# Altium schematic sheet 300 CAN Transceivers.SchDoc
size Letter; Organization: Toradex Solutions Inc.; Address1: 6415 Northwest Drive; Address2: Mississauga, ON, L4V 1X1; Address3: Canada
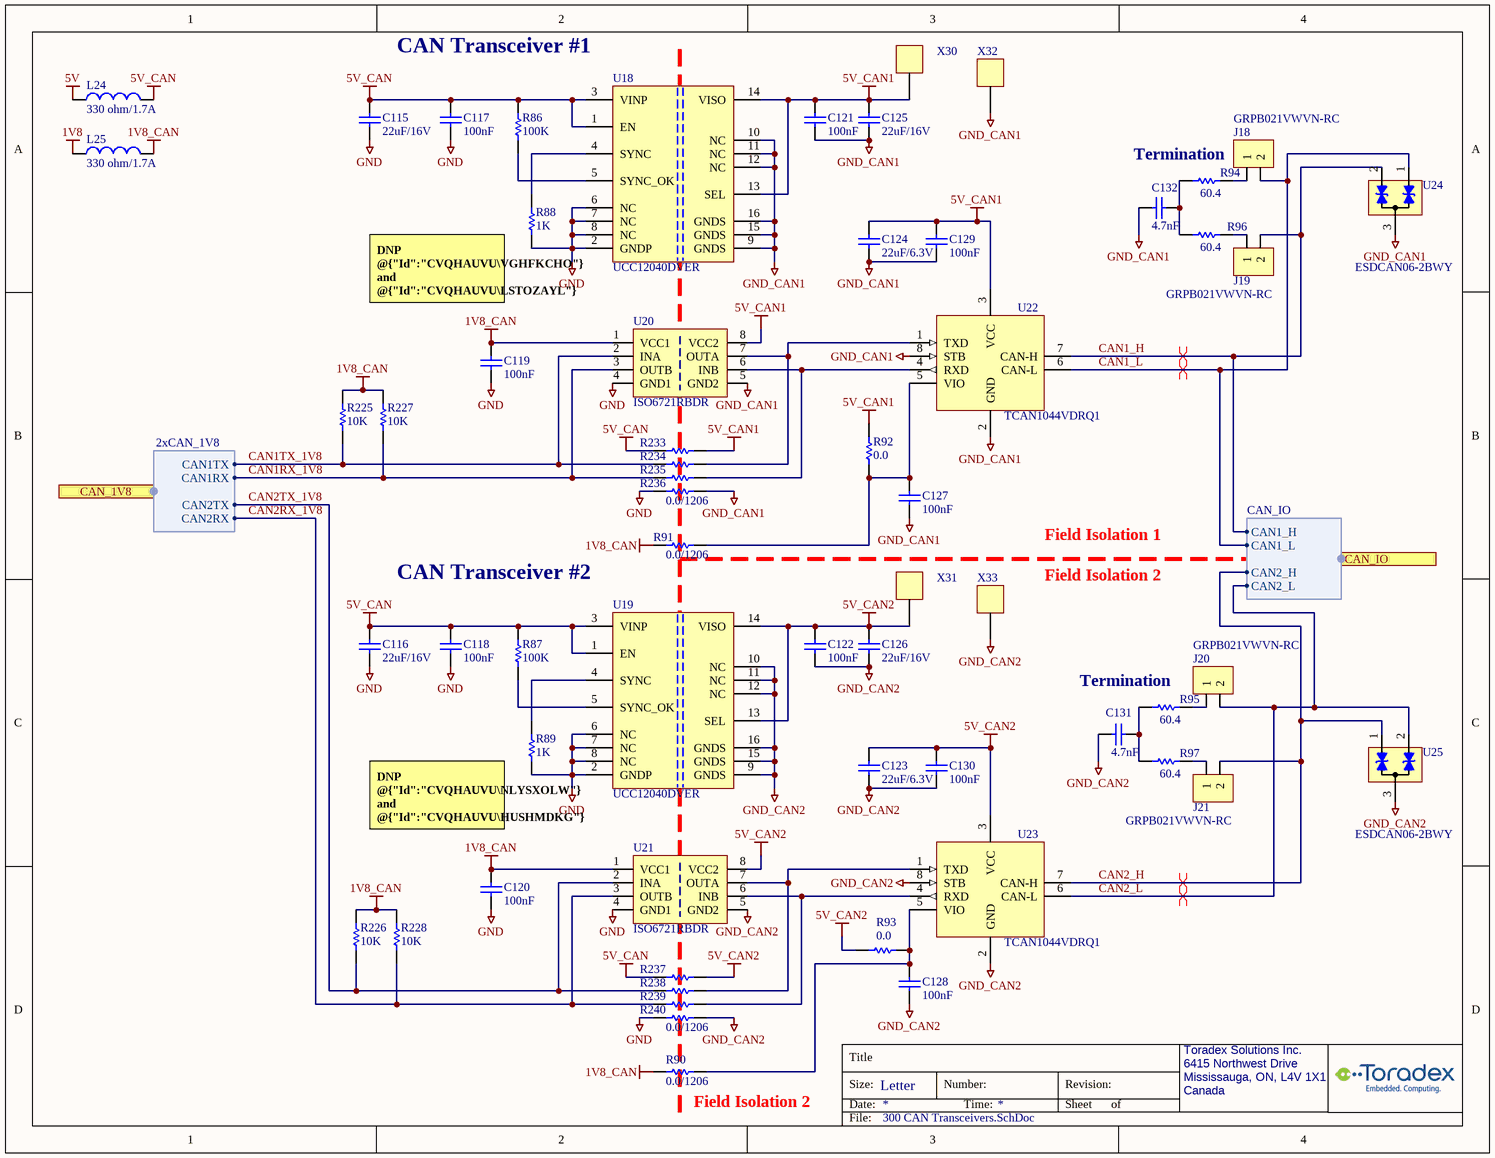
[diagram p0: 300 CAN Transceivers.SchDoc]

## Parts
C115  value 22uF/16V  [C/0805]  (hidden comment: 1314-Cap-0805-22uF/16V)
C116  value 22uF/16V  [C/0805]  (hidden comment: 1314-Cap-0805-22uF/16V)
C117  100nF  [C0402_CAPC1005L]
C118  100nF  [C0402_CAPC1005L]
C119  100nF  [C0402_CAPC1005L]
C120  100nF  [C0402_CAPC1005L]
C121  100nF  [C0402_CAPC1005L]
C122  100nF  [C0402_CAPC1005L]
C123  22uF/6.3V  [C0402_CAPC1005L]
C124  22uF/6.3V  [C0402_CAPC1005L]
C125  value 22uF/16V  [C/0805]  (hidden comment: 1314-Cap-0805-22uF/16V)
C126  value 22uF/16V  [C/0805]  (hidden comment: 1314-Cap-0805-22uF/16V)
C127  100nF  [C0402_CAPC1005L]
C128  100nF  [C0402_CAPC1005L]
C129  100nF  [C0402_CAPC1005L]
C130  100nF  [C0402_CAPC1005L]
C131  value 4.7nF  [C/0603]  (hidden comment: 0346-Cap-0603-4.7nF)
C132  value 4.7nF  [C/0603]  (hidden comment: 0346-Cap-0603-4.7nF)
J18  GRPB021VWVN-RC  [CONN_WVN-RC_SUL]
J19  GRPB021VWVN-RC  [CONN_WVN-RC_SUL]
J20  GRPB021VWVN-RC  [CONN_WVN-RC_SUL]
J21  GRPB021VWVN-RC  [CONN_WVN-RC_SUL]
L24  value 330 ohm/1.7A  [INDC1608x095]  (hidden comment: 0405-Fer-0603-330ohm/1.7A)
L25  value 330 ohm/1.7A  [INDC1608x095]  (hidden comment: 0405-Fer-0603-330ohm/1.7A)
R86  value 100K  [R0402_RESC1005L]  (hidden comment: 1977-Res-0402-100K)
R87  value 100K  [R0402_RESC1005L]  (hidden comment: 1977-Res-0402-100K)
R88  value 1K  [R0402_RESC1005L]  (hidden comment: 1650-Res-0402-1K)
R89  value 1K  [R0402_RESC1005L]  (hidden comment: 1650-Res-0402-1K)
R90  value 0.0/1206  [R/1206]  (hidden comment: 0038-Res-1206-0.0ohm)
R91  value 0.0/1206  [R/1206]  (hidden comment: 0038-Res-1206-0.0ohm)
R92  value 0.0  [R/0603]  (hidden comment: 0195-Res-0603-0.0ohm)
R93  value 0.0  [R/0603]  (hidden comment: 0195-Res-0603-0.0ohm)
R94  value 60.4  [R/0603]  (hidden comment: 2199-Res-0603-60.4)
R95  value 60.4  [R/0603]  (hidden comment: 2199-Res-0603-60.4)
R96  value 60.4  [R/0603]  (hidden comment: 2199-Res-0603-60.4)
R97  value 60.4  [R/0603]  (hidden comment: 2199-Res-0603-60.4)
R225  value 10K  [R0402_RESC1005L]  (hidden comment: 1572-Res-0402-10K)
R226  value 10K  [R0402_RESC1005L]  (hidden comment: 1572-Res-0402-10K)
R227  value 10K  [R0402_RESC1005L]  (hidden comment: 1572-Res-0402-10K)
R228  value 10K  [R0402_RESC1005L]  (hidden comment: 1572-Res-0402-10K)
R233  0038-Res-1206-0.0ohm  [R/1206]  (value not drawn)
R234  0038-Res-1206-0.0ohm  [R/1206]  (value not drawn)
R235  0038-Res-1206-0.0ohm  [R/1206]  (value not drawn)
R236  value 0.0/1206  [R/1206]  (hidden comment: 0038-Res-1206-0.0ohm)
R237  0038-Res-1206-0.0ohm  [R/1206]  (value not drawn)
R238  0038-Res-1206-0.0ohm  [R/1206]  (value not drawn)
R239  0038-Res-1206-0.0ohm  [R/1206]  (value not drawn)
R240  value 0.0/1206  [R/1206]  (hidden comment: 0038-Res-1206-0.0ohm)
U18  UCC12040DVER  [SOIC-16]
U19  UCC12040DVER  [SOIC-16]
U20  ISO6721RBDR  [SOIC-8]
U21  ISO6721RBDR  [SOIC-8]
U22  TCAN1044VDRQ1  [SOIC-8]
U23  TCAN1044VDRQ1  [SOIC-8]
U24  ESDCAN06-2BWY  [SOT-323]
U25  ESDCAN06-2BWY  [SOT-323]
X30  000-TestPoint  [TestPoint_1]  (value not drawn)
X31  000-TestPoint  [TestPoint_1]  (value not drawn)
X32  000-TestPoint  [TestPoint_1]  (value not drawn)
X33  000-TestPoint  [TestPoint_1]  (value not drawn)

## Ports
CAN_1V8 (harness 2xCAN_1V8), CAN_IO (harness CAN_IO)

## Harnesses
2xCAN_1V8: CAN1TX, CAN1RX, CAN2TX, CAN2RX
CAN_IO: CAN2_H, CAN2_L, CAN1_H, CAN1_L

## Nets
1V8: L25.1
1V8_CAN: C119.1 C120.1 L25.2 R90.1 R91.2 R225.1 R226.1 R227.1 R228.1 U20.1(VCC1) U21.1(VCC1)
5V: L24.1
5V_CAN: C115.2 C116.2 C117.1 C118.1 L24.2 R86.2 R87.2 R233.2 R237.1 U18.1(EN) U18.3(VINP) U19.1(EN) U19.3(VINP)
5V_CAN1: C121.1 C124.2 C125.2 C129.1 R92.2 R233.1 U18.13(SEL) U18.14(VISO) U20.8(VCC2) U22.3(VCC) X30.1
5V_CAN2: C122.1 C123.2 C126.2 C130.1 R93.2 R237.2 U19.13(SEL) U19.14(VISO) U21.8(VCC2) U23.3(VCC) X31.1
GND: C115.1 C116.1 C117.2 C118.2 C119.2 C120.2 R88.1 R89.1 R236.1 R240.1 U18.2(GNDP) U18.6(NC) U18.7(NC) U18.8(NC) U19.2(GNDP) U19.6(NC) U19.7(NC) U19.8(NC) U20.4(GND1) U21.4(GND1)
GND_CAN1: C121.2 C124.1 C125.1 C127.1 C129.2 C132.1 R236.2 U18.9(GNDS) U18.10(NC) U18.11(NC) U18.12(NC) U18.15(GNDS) U18.16(GNDS) U20.5(GND2) U22.2(GND) U22.8(STB) U24.3 X32.1
GND_CAN2: C122.2 C123.1 C126.1 C128.1 C130.2 C131.1 R240.2 U19.9(GNDS) U19.10(NC) U19.11(NC) U19.12(NC) U19.15(GNDS) U19.16(GNDS) U21.5(GND2) U23.2(GND) U23.8(STB) U25.3 X33.1
CAN1_H: J19.2 U22.7(CAN-H) U24.2 ; port CAN_IO.CAN1_H
CAN1_L: J18.2 U22.6(CAN-L) U24.1 ; port CAN_IO.CAN1_L
CAN1RX_1V8: R227.2 R235.1 U20.3(OUTB) ; port CAN_1V8.CAN1RX
CAN1TX_1V8: R225.2 R234.1 U20.2(INA) ; port CAN_1V8.CAN1TX
CAN2_H: J21.2 U23.7(CAN-H) U25.1 ; port CAN_IO.CAN2_H
CAN2_L: J20.2 U23.6(CAN-L) U25.2 ; port CAN_IO.CAN2_L
CAN2RX_1V8: R228.2 R239.1 U21.3(OUTB) ; port CAN_1V8.CAN2RX
CAN2TX_1V8: R226.2 R238.1 U21.2(INA) ; port CAN_1V8.CAN2TX
NetC127_2: C127.2 R91.1 R92.1 U22.5(VIO)
NetC128_2: C128.2 R90.2 R93.1 U23.5(VIO)
NetC131_2: C131.2 R95.1 R97.1
NetC132_2: C132.2 R94.1 R96.1
NetJ18_1: J18.1 R94.2
NetJ19_1: J19.1 R96.2
NetJ20_1: J20.1 R95.2
NetJ21_1: J21.1 R97.2
NetR86_1: R86.1 U18.5(SYNC_OK)
NetR87_1: R87.1 U19.5(SYNC_OK)
NetR88_2: R88.2 U18.4(SYNC)
NetR89_2: R89.2 U19.4(SYNC)
NetR234_2: R234.2 U20.7(OUTA) U22.1(TXD)
NetR235_2: R235.2 U20.6(INB) U22.4(RXD)
NetR238_2: R238.2 U21.7(OUTA) U23.1(TXD)
NetR239_2: R239.2 U21.6(INB) U23.4(RXD)

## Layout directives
differential pair; differential pair class CAN: CAN1_H, CAN1_L, CAN2_H, CAN2_L

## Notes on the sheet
- CAN Transceiver #1
- Termination
- (near R88) DNP @{"Id":"CVQHAUVU\VGHFKCHO"} and @{"Id":"CVQHAUVU\LSTOZAYL"} if @{"Id":"CVQHAUVU\EXQIJSEJ","ObjectType":2}, @{"Id":"CVQHAUVU\FPYPKWKA","ObjectType":2}, @{"Id":"CVQHAUVU\KOMEBSIN","ObjectType":2}, @{"Id":"CVQHAUVU\FIXPCWRI","ObjectType":2} and @{"Id":"CVQHAUVU\DUMHUNPN","ObjectType":2} are mounted.
- Field Isolation 1
- CAN Transceiver #2
- Field Isolation 2
- (near R95) Termination
- (near R89) DNP @{"Id":"CVQHAUVU\NLYSXOLW"} and @{"Id":"CVQHAUVU\HUSHMDKG"} if @{"Id":"CVQHAUVU\KSCWPYYC","ObjectType":2}, @{"Id":"CVQHAUVU\LTHGTOLS","ObjectType":2}, @{"Id":"CVQHAUVU\JVBMRTFO","ObjectType":2}, @{"Id":"CVQHAUVU\RWBWDMFZ","ObjectType":2} and @{"Id":"CVQHAUVU\PNPZHAQY","ObjectType":2} are mounted.
- (near R90) Field Isolation 2

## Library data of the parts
C115 C116 C125 C126 = 1314-Cap-0805-22uF/16V: (-55 to 85 DegC) CAP CER 22uF 16V X5R 0805; MfrNo: CL21A226MOQNNNE; Mfr: Samsung; PN: 1314; Alt: CL21A226MOCLRNC,CL21A226KOQNNNG,GRM21BR61C226ME44L,EMK212BBJ226MG-T
C117-C122 C129 C130 = 1566-Cap-0402-100nF/50V: (-55 to 125 DegC AEC) Cap Ceramic 0.1uF 50V X7R 10% 0402; MfrNo: GRT155R71H104KE01D; Mfr: Murata; Alt: CL05B104KB54PNC,GCM155R71H104ME02D,GCM155R71H104KE02D,GCM155R71H104KE02J; PN: 1566
C123 C124 = 2404-Cap-0402-22uF/6.3V: (-55 to 85 DegC) CAP CER 22UF 6.3V 20% X5R 0402; MfrNo: GRM155R60J226ME11D; Mfr: Murata; PN: 2404
C127 C128 = 1566-Cap-0402-100nF/50V: (-55 to 125 DegC AEC) Cap Ceramic 0.1uF 50V X7R 10% 0402; Mfr: Murata; MfrNo: GRT155R71H104KE01D; PN: 1566; Alt: CL05B104KB54PNC,GCM155R71H104ME02D,GCM155R71H104KE02D,GCM155R71H104KE02J
C131 C132 = 0346-Cap-0603-4.7nF: CAP CER 4700PF 50V 5% NP0 0603; MfrNo: GRM1885C1H472JA01D; Mfr: Murata Electronics North America; PN: 346; Alt: 445-13986-1-ND; Alt2: 445-6912-1-ND
J18-J21 = 2350-CONN HEADER VERT 2POS 1.27MM: (-40 to 105 DegC) CONN HEADER VERT 2POS 1.27MM GOLD; Mfr: Sullins; PN: 2350
L24 L25 = 0405-Fer-0603-330ohm/1.7A: (-55 to 125 DegC) FERRITE BEAD 330 OHM 0603 1.7A 80mohm, typ 48mohm; Mfr: TDK Corporation; MfrNo: MPZ1608S331ATA00; PN: 405; TR: 445-5221-2-ND; DR: 445-5221-6-ND; DR2: 810-MPZ1608S331ATA00
R86 R87 = 1977-Res-0402-100K: (-55 to 155 DegC) RES 100K OHM 1/16W 1% 0402 SMD; Mfr: Yageo; MfrNo: RC0402FR-07100KL; PN: 1977
R88 R89 = 1650-Res-0402-1K: (-55 to 155 DegC AEC) RES 1K OHM 1% 1/16W 100ppm 0402; Mfr: TE Connectivity; MfrNo: CRGCQ0402F1K0; PN: 1650; Alt: CR0402AFX-1001GLF,AC0402FR-131KL,AC0402FR-071KL
R90 R91 R233-R240 = 0038-Res-1206-0.0ohm: (-55 to 155 DegC) RES 0.0 OHM 1/4W JUMPER 1206; Mfr: TE; MfrNo: 1623693-1; PN: 38; Alt: 311-0.0ERCT-ND; Alt2: RMCF1206ZT0R00CT-ND
R92 R93 = 0195-Res-0603-0.0ohm: RES 0.0 OHM 1/10W JUMP 0603; Mfr: Samsung; MfrNo: RC1608J000CS; Alt: 311-0.0GRCT-ND; Alt2: A106051CT-ND; PN: 195; TR: 1276-3510-2-ND
R94-R97 = 2199-Res-0603-60.4: (-55 to 155 DegC) RES SMD 60.4 OHM 1% 1/10W 0603; Mfr: Bourns; MfrNo: CR0603-FX-60R4ELF; Desc: (-55 to 155 DegC) RES SMD 60.4k OHM 1% 1/10W 0603; PN: 2199
R225-R228 = 1572-Res-0402-10K: (-55 to 155 DegC AEC) RES 10K OHM 1% 1/16W 100ppm 0402; Mfr: Stackpole Electronics; MfrNo: RMCF0402FT10K0; Alt: AC0402FR-0710KL,AC0402FR-1310KL,CRGCQ0402F10K; PN: 1572
U18 U19 = 2065-UCC12040DVER: (-40 to 125 DegC) IC Isolated DC DC Converter-Output 3.3V, 5V 140mA, 4.5V-5.5V Input; Mfr: Texas Instruments; PN: 2065
U20 U21 = 2198-ISO6721RBDR: (-40 to 125 DegC) IC DGTL ISO GENERAL-PURPOSE, DUAL-CHANNEL, 1x In, 1x Out 1.71-5.5V; Mfr: Texas Instruments; PN: 2198
U22 U23 = 1620-TCAN1044VDRQ1: (-40 to 125 DegC) IC TXRX CAN FD 8MBPS Vio:1.8-5V Standby 8SOIC; Mfr: Texas Instruments; PN: 1620
U24 U25 = 1564-ESDCAN06-2BWY: (-55 to 175 DegC AEC) TVS DIODE CAN 2-ch 35V Vcl: 59Vmax, 8/20:3A, ESD:30KV air,30KV cont, 15pF, SOT323; Mfr: STMicroelectronics; PN: 1564
X30-X33 = 000-TestPoint: Note: this is PCB footprint only, no parts to buy or assemble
